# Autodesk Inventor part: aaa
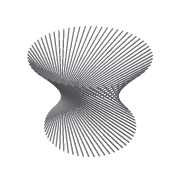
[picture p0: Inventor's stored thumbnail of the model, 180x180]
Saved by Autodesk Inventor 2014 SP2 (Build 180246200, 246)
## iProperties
Created: 2015-04
Part Number: aaa
Material: Generic
Document SubType Name: Modeling
Designer: SFC
Density: 1 g/cm^3
Appearance: Default
Author: SFC
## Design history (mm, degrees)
sketch "3D Sketch1"
workplane "Work Plane1"
sketch "Sketch2"
  geometry: C1 r 1.809 at (0, 0); 1 further point
  constraints: 1 centre point
extrude "Extrusion1" new body sketch "Sketch2" distance "d0" = 336.75; taper "d1" = 0 deg
sketch "Sketch3"
  geometry: L1 (72.291, 310.961)-(72.291, -52.994); 1 further point
  constraints: 2 end point, 1 vertical
workaxis "Work Axis1"
body "Solid1"
pattern_circular "Circular Pattern1" dims "d3" = 360 deg
